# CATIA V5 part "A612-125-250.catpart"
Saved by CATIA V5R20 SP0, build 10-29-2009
Part number: A612-125-250
Source: Unknown
Property "A": "30.000"
Property "ARTICLENO": "A612-125-250"
Property "B": "50.000"
Property "BOMINFO": "A612-125-250"
Property "CODE": "A612-125-250"
Property "D": "22.000"
Property "FORM": "B"
Property "L": "250.000"
Property "L1": "45.000"
Property "L2": "80.000"
Property "L3": "0.000"
Property "LINA": "A612-125-250"
Property "NB": "A612-125-250"
Property "NBSYN": "$CODE."
Property "NN": "A612"
Property "NT": "CDI 3357 E-Type Wear Plates, steel and self-lubricating"
Property "SUPPLIER": "CF"
Property "T": "30.000"
Property "W": "125.000"
Bounding box of the stored display mesh (mm): x 0 to 30, y 0 to 250, z 0 to 125
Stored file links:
  C:\Users\Utente\Desktop\3D files A612\A612-125-250.catpart
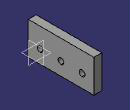
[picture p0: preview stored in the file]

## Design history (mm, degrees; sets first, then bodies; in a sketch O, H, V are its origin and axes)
Body1 "Geometry.1" (main body)
  Solid1 "A612-125-250.catpart": solid without history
